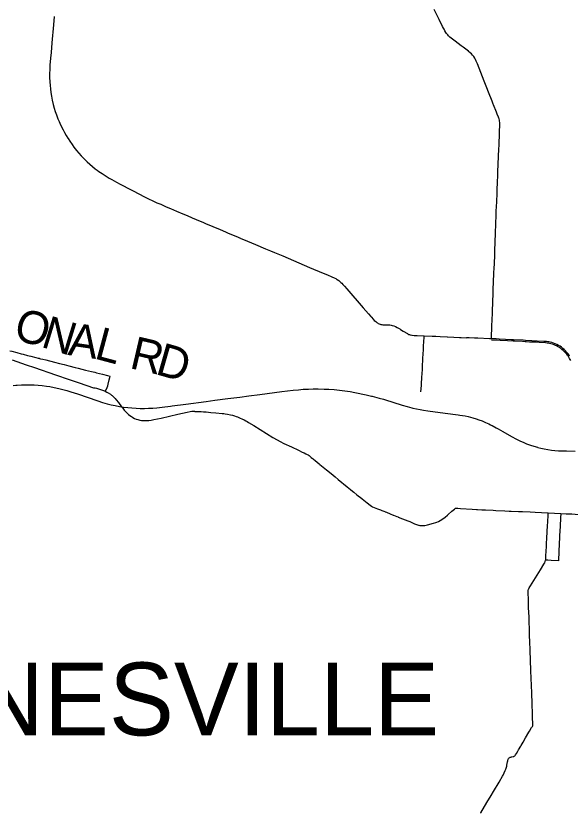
# Model space of a CAD drawing. Extents: x 1761803 to 2441803, y 509895 to 949895.
# Drawn here: x 2092620 to 2107842, y 793748 to 815637 of the extents above; entities that cross this region are included whole.
import ezdxf

# ---------------------------------------------------------------- set-up
doc = ezdxf.new("R2010")
doc.units = 0
for name, color, linetype in [('GM_X_County_Road', 7, 'Continuous'), ('GM_X_Minor_Lake', 7, 'Continuous'), ('GM_X_Minor_River', 7, 'Continuous'), ('GM_X_Minor_River_Text', 7, 'Continuous')]:
    doc.layers.add(name, color=color, linetype=linetype)

msp = doc.modelspace()

# ---------------------------------------------------------------- linework, layer by layer
at = {"layer": 'GM_X_County_Road'}
for points in [[(2092455, 806443), (2092505, 806429), (2092646, 806392), (2092760, 806361)], [(2092760, 806361), (2092817, 806345), (2092934, 806316), (2093027, 806293), (2093170, 806258), (2093232, 806242), (2093256, 806236)], [(2093256, 806236), (2093264, 806234), (2093295, 806225), (2093357, 806209), (2093438, 806189), (2093676, 806130), (2093819, 806095), (2093947, 806063), (2094073, 806030), (2094248, 805987), (2094327, 805967), (2094533, 805914), (2094612, 805895), (2094692, 805874), (2094787, 805851), (2094835, 805840), (2094994, 805799), (2095137, 805763), (2095207, 805746)], [(2095069, 805330), (2095094, 805368), (2095107, 805391), (2095125, 805433), (2095141, 805481), (2095155, 805529), (2095183, 805642), (2095198, 805706), (2095207, 805746)]]:
    msp.add_lwpolyline(points, dxfattribs=at)
at = {"layer": 'GM_X_Minor_Lake'}
for points in [[(2105732, 813212), (2105699, 813295), (2105599, 813546), (2105553, 813661), (2105518, 813750), (2105478, 813848), (2105297, 814319), (2105266, 814394), (2105245, 814437), (2105222, 814479), (2105195, 814519), (2105166, 814557), (2105134, 814592), (2105099, 814625), (2105055, 814661), (2105049, 814666), (2104906, 814776), (2104853, 814815), (2104684, 814944), (2104579, 815025), (2104541, 815057), (2104504, 815092), (2104481, 815117), (2104449, 815157), (2104430, 815184), (2104403, 815227), (2104379, 815270), (2104364, 815300), (2104342, 815345), (2104247, 815540), (2104220, 815596), (2104112, 815815)], [(2093672, 815619), (2093653, 815393), (2093608, 814900), (2093587, 814630), (2093573, 814480)], [(2093573, 814480), (2093555, 814285), (2093547, 814170), (2093545, 814058), (2093544, 813948), (2093549, 813828), (2093556, 813727), (2093566, 813631), (2093580, 813531), (2093596, 813434), (2093618, 813322), (2093645, 813207), (2093672, 813103), (2093701, 813013), (2093731, 812923), (2093772, 812813), (2093803, 812738), (2093843, 812650), (2093913, 812508), (2093951, 812436), (2094000, 812350), (2094045, 812277), (2094051, 812269), (2094097, 812196), (2094160, 812104), (2094212, 812035), (2094282, 811946), (2094347, 811869), (2094413, 811796), (2094492, 811713), (2094576, 811632), (2094646, 811568), (2094724, 811501), (2094798, 811440), (2094849, 811401), (2094897, 811367), (2094984, 811306), (2095097, 811233), (2095180, 811183), (2095255, 811141), (2095383, 811072), (2095486, 811018), (2095589, 810965), (2095674, 810920)], [(2105795, 809710), (2105801, 809888), (2105805, 810000), (2105809, 810095), (2105810, 810130), (2105813, 810196), (2105814, 810220), (2105815, 810245), (2105823, 810427), (2105826, 810508), (2105828, 810573), (2105835, 810736), (2105842, 810916), (2105845, 811015), (2105855, 811310), (2105857, 811359), (2105876, 811774), (2105878, 811837), (2105881, 811919), (2105890, 812140), (2105899, 812369), (2105903, 812457), (2105904, 812485), (2105911, 812619), (2105911, 812628), (2105911, 812668), (2105909, 812715), (2105905, 812747), (2105900, 812778), (2105892, 812808), (2105885, 812829), (2105877, 812853), (2105843, 812937), (2105822, 812990), (2105738, 813198), (2105732, 813212)], [(2095674, 810920), (2095767, 810871)], [(2095767, 810871), (2095836, 810835), (2096000, 810748), (2096152, 810668), (2096210, 810638), (2096283, 810601), (2096358, 810567), (2096363, 810565), (2096494, 810509), (2096599, 810464), (2096659, 810438), (2096750, 810399), (2096870, 810347), (2097035, 810275), (2097202, 810206), (2097323, 810155), (2097459, 810096), (2097685, 810000), (2097753, 809971), (2097828, 809939), (2098230, 809770), (2098374, 809708), (2098379, 809706), (2098432, 809684), (2098726, 809559), (2098760, 809545), (2098787, 809534), (2098799, 809529)], [(2105779, 809241), (2105784, 809381), (2105785, 809389), (2105795, 809710)], [(2098799, 809529), (2098873, 809499), (2099205, 809359), (2099478, 809243), (2099610, 809186), (2099719, 809140), (2099947, 809046), (2100098, 808981), (2100688, 808732)], [(2105726, 807982), (2105730, 808079), (2105733, 808161), (2105738, 808301), (2105739, 808324), (2105750, 808570), (2105751, 808611), (2105755, 808680), (2105771, 809037), (2105775, 809115), (2105775, 809119), (2105779, 809241)], [(2100688, 808732), (2101059, 808574), (2101181, 808523)], [(2101181, 808523), (2101301, 808473), (2101360, 808446), (2101404, 808425), (2101430, 808409), (2101446, 808400), (2101486, 808372), (2101511, 808352), (2101547, 808320), (2101570, 808297), (2101603, 808262), (2101620, 808243)], [(2101620, 808243), (2101647, 808213), (2101710, 808139), (2102158, 807622), (2102305, 807453), (2102371, 807379), (2102383, 807365)], [(2105701, 807283), (2105708, 807485), (2105720, 807823), (2105726, 807982)], [(2102383, 807365), (2102429, 807313), (2102465, 807276), (2102502, 807242), (2102530, 807220), (2102550, 807205), (2102570, 807194), (2102594, 807183), (2102626, 807172), (2102644, 807167), (2102671, 807161), (2102702, 807158), (2102748, 807157), (2102847, 807154), (2102889, 807151)], [(2105696, 807140), (2105701, 807283)], [(2102889, 807151), (2102895, 807150), (2102927, 807146), (2102959, 807139), (2103005, 807125), (2103051, 807106), (2103092, 807085), (2103164, 807042), (2103183, 807030), (2103261, 806981), (2103377, 806912), (2103386, 806906), (2103415, 806892), (2103430, 806886), (2103446, 806881), (2103462, 806876), (2103495, 806871), (2103506, 806870)], [(2105683, 806776), (2105696, 807140)], [(2103506, 806870), (2103560, 806866), (2103642, 806861), (2103837, 806852)], [(2103820, 806594), (2103824, 806673), (2103827, 806724), (2103831, 806782), (2103837, 806852)], [(2103837, 806852), (2104053, 806843)], [(2104053, 806843), (2104153, 806839), (2104272, 806834), (2104462, 806824), (2104478, 806823), (2104651, 806814), (2104804, 806807), (2104851, 806805), (2104995, 806798)], [(2104995, 806798), (2105008, 806805), (2105022, 806808), (2105042, 806809), (2105069, 806809), (2105220, 806801), (2105244, 806800), (2105306, 806797), (2105630, 806779), (2105645, 806778), (2105683, 806776)], [(2107861, 806174), (2107827, 806234), (2107806, 806269), (2107796, 806286), (2107784, 806306), (2107769, 806325), (2107752, 806347), (2107725, 806379), (2107691, 806415), (2107655, 806449), (2107617, 806481), (2107596, 806498), (2107577, 806512), (2107559, 806524), (2107537, 806538), (2107516, 806550), (2107496, 806563), (2107471, 806576), (2107443, 806589), (2107407, 806604), (2107359, 806621), (2107311, 806636), (2107281, 806643), (2107239, 806651), (2107216, 806654), (2107167, 806658), (2106991, 806669), (2106902, 806674), (2106728, 806683), (2106634, 806688), (2106613, 806689), (2106533, 806693), (2106316, 806704), (2106283, 806706), (2106120, 806714), (2105923, 806724), (2105813, 806730), (2105682, 806737)], [(2107829, 806295), (2107827, 806297), (2107814, 806319), (2107782, 806364), (2107748, 806406), (2107716, 806443), (2107682, 806477), (2107645, 806509), (2107606, 806539), (2107566, 806566), (2107524, 806591), (2107480, 806614), (2107436, 806634), (2107390, 806651), (2107343, 806665), (2107296, 806677), (2107258, 806685), (2107238, 806688), (2107199, 806693), (2107118, 806700), (2106938, 806709), (2106921, 806710), (2106790, 806717), (2106616, 806726), (2106556, 806729), (2106285, 806743), (2106237, 806746), (2106071, 806754), (2105892, 806764), (2105813, 806769), (2105683, 806776)], [(2103745, 805318), (2103747, 805350), (2103749, 805370), (2103751, 805414), (2103757, 805476), (2103761, 805511), (2103764, 805561), (2103770, 805685), (2103781, 805849), (2103784, 805898), (2103792, 806013), (2103800, 806210), (2103810, 806374), (2103814, 806447), (2103816, 806489), (2103818, 806538), (2103820, 806579), (2103820, 806594)]]:
    msp.add_lwpolyline(points, dxfattribs=at)
at = {"layer": 'GM_X_Minor_River'}
msp.add_lwpolyline([(2092543, 805488), (2092620, 805495), (2092657, 805498), (2092772, 805504), (2092886, 805507), (2093001, 805506), (2093116, 805503), (2093230, 805495), (2093344, 805485), (2093458, 805471), (2093555, 805457), (2093668, 805436), (2093796, 805409), (2093908, 805382), (2094018, 805352), (2094128, 805318), (2094315, 805256), (2094873, 805066), (2094999, 805026), (2095125, 804989), (2095236, 804961), (2095348, 804936), (2095461, 804914), (2095523, 804905), (2095575, 804897), (2095689, 804883), (2095803, 804872), (2095918, 804864), (2096033, 804860), (2096148, 804860), (2096263, 804862), (2096378, 804868), (2096492, 804878), (2096639, 804894), (2096867, 804923), (2096915, 804929), (2097290, 804978), (2097843, 805051), (2098087, 805082), (2098445, 805128), (2098770, 805171), (2099014, 805202), (2099323, 805241), (2099925, 805320), (2100234, 805358), (2100381, 805373), (2100511, 805384), (2100658, 805392), (2100789, 805396), (2100850, 805396), (2100921, 805395), (2101084, 805391), (2101215, 805385), (2101363, 805375), (2101509, 805361), (2101656, 805342), (2101802, 805321), (2101931, 805298), (2102242, 805236), (2102385, 805200), (2102407, 805195), (2102474, 805178), (2102600, 805143), (2102718, 805109), (2102742, 805102), (2103229, 804951), (2103371, 804909), (2103498, 804875), (2103520, 804870), (2103626, 804845), (2103723, 804825), (2103820, 804808), (2103934, 804792), (2104407, 804733), (2104766, 804685), (2104814, 804678), (2104884, 804667), (2104960, 804653), (2105040, 804635), (2105167, 804602), (2105262, 804575), (2105339, 804549), (2105431, 804514), (2105522, 804476), (2105611, 804434), (2105657, 804411), (2105678, 804401), (2105699, 804390), (2105815, 804328), (2105866, 804300), (2105996, 804225), (2106234, 804087), (2106254, 804077), (2106352, 804025), (2106421, 803990), (2106483, 803960), (2106554, 803928), (2106646, 803891), (2106754, 803852), (2106848, 803821), (2106943, 803794), (2106961, 803786), (2107038, 803770), (2107135, 803749), (2107232, 803731), (2107330, 803717), (2107428, 803706), (2107526, 803698), (2107657, 803693), (2107672, 803692), (2107742, 803691), (2107986, 803684)], dxfattribs=at)
at = {"layer": 'GM_X_Minor_River_Text'}
for points in [[(2092515, 806193), (2092902, 806060), (2093125, 805984), (2093711, 805783), (2094086, 805654), (2094354, 805561), (2094747, 805425)], [(2094747, 805425), (2094799, 805420), (2094835, 805412), (2095022, 805348), (2095069, 805330), (2095113, 805309), (2095157, 805285), (2095213, 805250), (2095242, 805227), (2095264, 805210), (2095283, 805193), (2095304, 805175), (2095316, 805163), (2095342, 805134), (2095374, 805097), (2095436, 805020), (2095523, 804905), (2095555, 804863), (2095596, 804811), (2095621, 804782), (2095639, 804761), (2095674, 804726), (2095710, 804692), (2095749, 804661), (2095790, 804633), (2095818, 804617), (2095833, 804608), (2095878, 804586), (2095924, 804568), (2095971, 804552), (2096019, 804539), (2096068, 804530), (2096117, 804525), (2096146, 804524), (2096167, 804523), (2096216, 804525), (2096266, 804529), (2096331, 804538), (2096412, 804554), (2096605, 804596), (2097070, 804701), (2097327, 804758), (2097407, 804773), (2097456, 804780), (2097481, 804783), (2097491, 804784), (2097500, 804784), (2097508, 804783), (2097517, 804782), (2097524, 804780), (2097533, 804777)], [(2097533, 804777), (2097568, 804779), (2097616, 804778), (2097653, 804777), (2097704, 804773), (2097776, 804768), (2097845, 804762), (2097976, 804750), (2098108, 804739), (2098286, 804723), (2098332, 804718), (2098370, 804713), (2098433, 804702), (2098514, 804686), (2098572, 804670), (2098628, 804653), (2098665, 804640), (2098707, 804624), (2098776, 804596), (2098828, 804573), (2098893, 804542), (2098939, 804517), (2098973, 804497), (2099010, 804476), (2099151, 804389), (2099681, 804064), (2099793, 803997), (2099879, 803950), (2099981, 803899), (2100188, 803800), (2100380, 803709), (2100487, 803659), (2100533, 803637), (2100581, 803615), (2100581, 803615)], [(2100581, 803615), (2100602, 803605), (2100645, 803582), (2100672, 803564), (2100709, 803534), (2100732, 803515), (2100769, 803485), (2100784, 803473), (2100796, 803463), (2100838, 803429), (2100952, 803333), (2100969, 803319), (2101147, 803173), (2101187, 803141), (2101331, 803023), (2101389, 802976), (2101475, 802906), (2101722, 802703), (2101808, 802632), (2101864, 802586), (2101899, 802561), (2101987, 802488), (2102121, 802382), (2102129, 802375), (2102270, 802262), (2102347, 802202), (2102388, 802176), (2102416, 802161), (2102461, 802141), (2102552, 802105), (2102636, 802072), (2102674, 802057), (2102750, 802025), (2102765, 802019), (2102796, 802008), (2102903, 801964), (2102985, 801931)], [(2104491, 801942), (2104595, 802035), (2104633, 802068), (2104667, 802096), (2104695, 802116), (2104718, 802117), (2104758, 802117), (2104831, 802113), (2105154, 802094), (2105268, 802086)], [(2105268, 802086), (2105295, 802084), (2105418, 802077), (2105474, 802075), (2105519, 802073), (2105733, 802064), (2105803, 802060), (2106046, 802049), (2106170, 802042)], [(2106170, 802042), (2106226, 802039), (2106422, 802030), (2106518, 802025), (2106536, 802025), (2106749, 802015), (2106879, 802009), (2107061, 802000), (2107243, 801991)], [(2102985, 801931), (2102994, 801928), (2103082, 801892), (2103116, 801878), (2103120, 801876), (2103238, 801829), (2103387, 801769), (2103436, 801750), (2103475, 801734), (2103573, 801694), (2103649, 801664), (2103680, 801654), (2103689, 801652), (2103711, 801646), (2103742, 801641), (2103774, 801640), (2103806, 801642), (2103854, 801648), (2103924, 801662), (2104089, 801706), (2104153, 801725), (2104186, 801737), (2104229, 801755), (2104274, 801779), (2104316, 801805), (2104357, 801833), (2104372, 801843), (2104411, 801871), (2104473, 801925), (2104491, 801942)], [(2107208, 801375), (2107209, 801399), (2107216, 801500), (2107223, 801616), (2107238, 801906), (2107243, 801991)], [(2107243, 801991), (2107585, 801977)], [(2107585, 801977), (2107580, 801854), (2107570, 801629), (2107556, 801361), (2107555, 801352), (2107544, 801104), (2107538, 800969), (2107535, 800893), (2107528, 800721), (2107526, 800674)], [(2107585, 801977), (2107737, 801967), (2107888, 801960), (2107985, 801956), (2108097, 801949), (2108208, 801943)], [(2107168, 800690), (2107172, 800709), (2107174, 800729), (2107180, 800811), (2107192, 801072), (2107208, 801375)], [(2106702, 799892), (2106709, 799906), (2106720, 799928), (2106753, 799985), (2106848, 800137), (2106935, 800276), (2106939, 800282), (2107030, 800428), (2107124, 800581), (2107140, 800609), (2107147, 800623), (2107158, 800653), (2107168, 800690)], [(2107526, 800674), (2107325, 800684), (2107235, 800689), (2107168, 800690)], [(2106822, 796140), (2106812, 796423), (2106811, 796453), (2106800, 796767), (2106791, 797029), (2106790, 797053), (2106767, 797656), (2106767, 797668), (2106748, 798208), (2106746, 798261), (2106740, 798421), (2106732, 798651), (2106727, 798809), (2106726, 798861), (2106723, 798932), (2106721, 799030), (2106716, 799128), (2106704, 799389), (2106702, 799459), (2106697, 799618), (2106692, 799782), (2106692, 799844), (2106694, 799862), (2106702, 799892)], [(2105389, 793748), (2105393, 793755), (2105559, 794034), (2105673, 794228), (2105741, 794342), (2105890, 794592), (2105941, 794677), (2105952, 794696), (2105986, 794757), (2106001, 794787), (2106011, 794808), (2106031, 794851), (2106058, 794912), (2106076, 794957), (2106087, 794985), (2106094, 795011), (2106101, 795034), (2106108, 795066), (2106124, 795150), (2106131, 795183), (2106136, 795203), (2106141, 795217), (2106146, 795229), (2106154, 795244), (2106163, 795255), (2106173, 795265), (2106186, 795274), (2106199, 795281), (2106214, 795286), (2106230, 795291), (2106245, 795293), (2106278, 795298), (2106295, 795301), (2106310, 795308), (2106324, 795318), (2106336, 795330), (2106346, 795344), (2106371, 795386), (2106405, 795443), (2106430, 795485), (2106488, 795584), (2106498, 795601), (2106555, 795697), (2106621, 795810), (2106711, 795968), (2106726, 795995), (2106786, 796095), (2106797, 796111), (2106807, 796123), (2106822, 796140)]]:
    msp.add_lwpolyline(points, dxfattribs=at)

# ---------------------------------------------------------------- texts
at = {"layer": 'GM_X_County_Road'}
for s, height, rotation, p in [('O', 900, 344.5404, (2092520, 806768)), ('N', 900, 342.8826, (2093277, 806559)), ('A', 900, 351.8726, (2094024, 806329)), ('L', 900, 345.0076, (2094743, 806237)), ('R', 900, 346.8991, (2095712, 805973)), ('D', 900, 344.0917, (2096421, 805809)), ('ZANESVILLE', 2000, 0, (2088042, 795881))]:
    msp.add_text(s, height=height, rotation=rotation, dxfattribs=at).set_placement(p)

doc.saveas('drawing.dxf')
